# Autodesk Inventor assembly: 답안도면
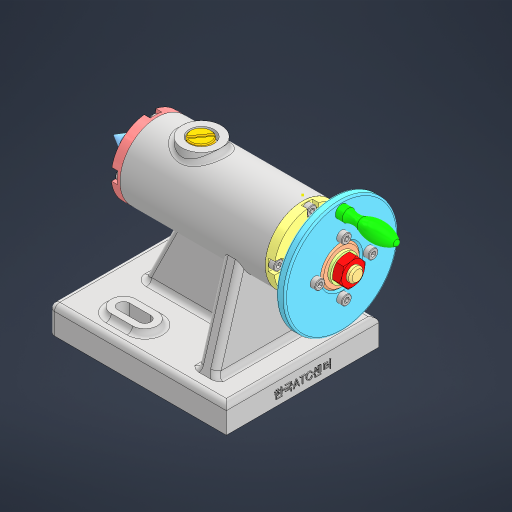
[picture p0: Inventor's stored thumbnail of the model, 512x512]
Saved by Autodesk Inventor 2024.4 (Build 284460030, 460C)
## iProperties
Created: 2026-09
Part Number: 답안도면
Document SubType Name: Assembly
Designer: user
Author: user
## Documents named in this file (18)
- C:\Users\user\Desktop\760903V1006\답안도면.iam
- C:\Users\user\Desktop\760903V1006\본체도면.ipt
- C:\Users\user\Desktop\760903V1006\가이드 부시\가이드 부시\가이드 부시.ipt
- C:\Users\user\Desktop\760903V1006\6각 구멍붙이 볼트 M3x8\6각 구멍붙이 볼트 M3x8\6각 구멍붙이 볼트 M3x8.ipt
- C:\Users\user\Desktop\760903V1006\슬리브\슬리브\슬리브.ipt
- C:\Users\user\Desktop\760903V1006\센터홀더\센터홀더\센터홀더.ipt
- C:\Users\user\Desktop\760903V1006\멈춤나사 M3\멈춤나사 M3\멈춤나사 M3.ipt
- C:\Users\user\Desktop\760903V1006\센터\센터\센터.ipt
- C:\Users\user\Desktop\760903V1006\커버\커버\커버.ipt
- C:\Users\user\Desktop\760903V1006\부시\부시\부시.ipt
- C:\Users\user\Desktop\760903V1006\나사축\나사축\나사축.ipt
- C:\Users\user\Desktop\760903V1006\평행 키 4x4x10\평행 키 4x4x10\평행 키 4x4x10.ipt
- C:\Users\user\Desktop\760903V1006\플랜지\플랜지\플랜지.ipt
- C:\Users\user\Desktop\760903V1006\돌림판\돌림판\돌림판.ipt
- C:\Users\user\Desktop\760903V1006\평 와셔 M8\평 와셔 M8\평 와셔 M8.ipt
- C:\Users\user\Desktop\760903V1006\6각 너트 M8\6각 너트 M8\6각 너트 M8.ipt
- C:\Users\user\Desktop\760903V1006\핸들\핸들\핸들.ipt
- C:\Users\user\Desktop\760903V1006\스톱퍼\스톱퍼\스톱퍼.ipt
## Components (16 placed, 5 different names)
1. 가이드 부시:1 — 플러쉬:1
2. 플랜지:1 — 각도:3
3. 6각 너트 M8:1
4. 핸들:1
5. 6각 구멍붙이 볼트 M3x8:1
6. 6각 구멍붙이 볼트 M3x8:2
7. 6각 구멍붙이 볼트 M3x8:3
8. 6각 구멍붙이 볼트 M3x8:4
9. 6각 구멍붙이 볼트 M3x8:5
10. 6각 구멍붙이 볼트 M3x8:7
11. 6각 구멍붙이 볼트 M3x8:8
12. 6각 구멍붙이 볼트 M3x8:9
13. 6각 구멍붙이 볼트 M3x8:6
14. 6각 구멍붙이 볼트 M3x8:10
15. 6각 구멍붙이 볼트 M3x8:11
16. 6각 구멍붙이 볼트 M3x8:12
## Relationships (2: Flush 1, Angle 1)
- 플러쉬:1 [Flush]: 가이드 부시:1
- 각도:3 [Angle]: 플랜지:1
